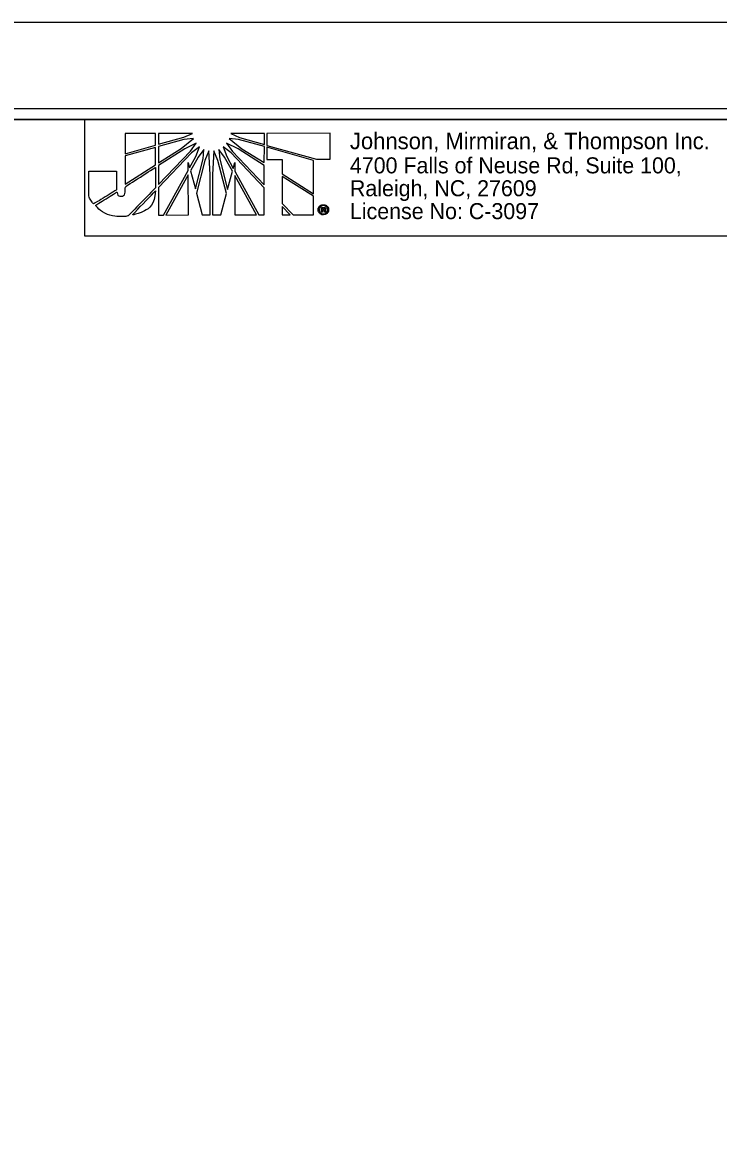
# Model space of a CAD drawing. Extents: x 1640342 to 1730599, y 538663 to 843747.
# Drawn here: x 1730101.1 to 1730133.5, y 540303.4 to 540355.9 of the extents above; entities that cross this region are included whole.
import ezdxf

# ---------------------------------------------------------------- set-up
doc = ezdxf.new("R2010")
doc.units = 0
for name, color, linetype in [('Prop Dimension Text', 7, 'Continuous'), ('Sheet Plan CELL', 7, 'Continuous'), ('Sheet Plot Border Inside CELL', 7, 'Continuous'), ('Sheet Plot Border Outside CELL', 7, 'Continuous')]:
    doc.layers.add(name, color=color, linetype=linetype)

msp = doc.modelspace()

# ---------------------------------------------------------------- linework, layer by layer
at = {"layer": 'Prop Dimension Text'}
for p, q in [((1730107.302, 540350.759), (1730105.899, 540350.758)), ((1730105.899, 540350.758), (1730105.9, 540349.827)), ((1730107.302, 540350.218), (1730107.302, 540350.759)), ((1730109.027, 540350.768), (1730107.448, 540350.767)), ((1730107.448, 540350.767), (1730107.448, 540350.264)), ((1730107.448, 540350.264), (1730108.624, 540350.589)), ((1730108.624, 540350.589), (1730109.027, 540350.768)), ((1730112.37, 540350.764), (1730110.814, 540350.77)), ((1730110.814, 540350.77), (1730111.208, 540350.585)), ((1730111.208, 540350.585), (1730112.37, 540350.26)), ((1730112.37, 540350.26), (1730112.37, 540350.764)), ((1730115.428, 540350.774), (1730112.479, 540350.771)), ((1730112.479, 540350.771), (1730112.479, 540350.23)), ((1730115.43, 540349.566), (1730115.428, 540350.774)), ((1730105.9, 540349.827), (1730107.302, 540350.218)), ((1730107.302, 540350.116), (1730105.9, 540349.721)), ((1730107.303, 540349.303), (1730107.302, 540350.116)), ((1730108.624, 540350.481), (1730107.448, 540350.155)), ((1730107.448, 540350.155), (1730107.449, 540349.396)), ((1730107.449, 540349.396), (1730108.502, 540350.064)), ((1730108.664, 540350.048), (1730107.449, 540349.273)), ((1730108.502, 540350.064), (1730109.082, 540350.537)), ((1730109.082, 540350.537), (1730108.624, 540350.481)), ((1730109.198, 540350.319), (1730108.664, 540350.048)), ((1730108.928, 540349.939), (1730109.198, 540350.319)), ((1730109.361, 540350.15), (1730108.988, 540349.863)), ((1730109.19, 540349.701), (1730109.361, 540350.15)), ((1730110.449, 540350.151), (1730110.621, 540349.702)), ((1730110.822, 540349.864), (1730110.449, 540350.151)), ((1730110.613, 540350.32), (1730110.884, 540349.934)), ((1730111.155, 540350.05), (1730110.613, 540350.32)), ((1730110.736, 540350.538), (1730111.324, 540350.057)), ((1730111.169, 540350.483), (1730110.736, 540350.538)), ((1730112.362, 540349.285), (1730111.155, 540350.05)), ((1730112.37, 540350.153), (1730111.169, 540350.483)), ((1730111.324, 540350.057), (1730112.362, 540349.41)), ((1730112.362, 540349.41), (1730112.37, 540350.153)), ((1730112.479, 540350.23), (1730112.479, 540350.213)), ((1730112.479, 540350.213), (1730114.802, 540349.565)), ((1730112.479, 540350.13), (1730112.479, 540350.121)), ((1730114.654, 540349.512), (1730112.479, 540350.13)), ((1730112.479, 540350.121), (1730112.48, 540349.556)), ((1730105.9, 540349.721), (1730105.901, 540348.413)), ((1730107.45, 540348.398), (1730108.928, 540349.939)), ((1730108.988, 540349.863), (1730107.45, 540348.25)), ((1730108.896, 540349.166), (1730109.19, 540349.701)), ((1730109.285, 540349.668), (1730108.936, 540349.034)), ((1730109.161, 540348.191), (1730109.523, 540349.592)), ((1730109.562, 540350.025), (1730109.285, 540349.668)), ((1730109.523, 540349.592), (1730109.562, 540350.025)), ((1730109.794, 540349.963), (1730109.602, 540349.514)), ((1730109.855, 540348.856), (1730109.794, 540349.963)), ((1730110.025, 540349.963), (1730109.954, 540348.856)), ((1730110.211, 540349.514), (1730110.025, 540349.963)), ((1730110.25, 540350.026), (1730110.296, 540349.577)), ((1730110.521, 540349.67), (1730110.25, 540350.026)), ((1730110.296, 540349.577), (1730110.661, 540348.16)), ((1730110.885, 540349.012), (1730110.521, 540349.67)), ((1730110.621, 540349.702), (1730110.922, 540349.144)), ((1730112.363, 540348.241), (1730110.822, 540349.864)), ((1730110.884, 540349.934), (1730112.363, 540348.386)), ((1730112.48, 540349.556), (1730113.2, 540349.556)), ((1730113.2, 540349.556), (1730113.201, 540348.883)), ((1730114.802, 540349.565), (1730115.43, 540349.566)), ((1730105.901, 540348.413), (1730107.303, 540349.303)), ((1730107.449, 540349.273), (1730107.45, 540348.398)), ((1730107.683, 540346.977), (1730108.827, 540349.05)), ((1730108.827, 540349.05), (1730108.826, 540349.42)), ((1730108.826, 540349.42), (1730108.896, 540349.166)), ((1730108.936, 540349.034), (1730109.161, 540348.191)), ((1730109.602, 540349.514), (1730109.208, 540347.997)), ((1730110.615, 540347.975), (1730110.211, 540349.514)), ((1730110.661, 540348.16), (1730110.885, 540349.012)), ((1730110.922, 540349.144), (1730110.994, 540349.422)), ((1730110.994, 540349.422), (1730110.994, 540349.013)), ((1730110.994, 540349.013), (1730112.116, 540346.981)), ((1730112.363, 540348.386), (1730112.362, 540349.285)), ((1730114.655, 540347.963), (1730114.654, 540349.512)), ((1730108.827, 540348.848), (1730107.792, 540346.977)), ((1730108.838, 540346.978), (1730108.827, 540348.848)), ((1730109.857, 540346.986), (1730109.855, 540348.856)), ((1730109.954, 540348.856), (1730109.956, 540346.986)), ((1730112.001, 540346.988), (1730110.994, 540348.811)), ((1730110.994, 540348.811), (1730110.996, 540346.987)), ((1730113.201, 540348.883), (1730114.655, 540347.963)), ((1730113.201, 540348.767), (1730113.202, 540347.512)), ((1730114.655, 540347.854), (1730113.201, 540348.767)), ((1730107.45, 540348.25), (1730107.451, 540346.976)), ((1730109.208, 540347.997), (1730109.472, 540346.985)), ((1730110.345, 540346.986), (1730110.615, 540347.975)), ((1730112.364, 540346.981), (1730112.363, 540348.241)), ((1730113.202, 540347.512), (1730113.705, 540346.982)), ((1730114.656, 540346.983), (1730114.655, 540347.854)), ((1730115.113, 540347.457), (1730115.113, 540347.413)), ((1730115.113, 540347.413), (1730115.113, 540347.457)), ((1730107.451, 540346.976), (1730107.683, 540346.977)), ((1730107.792, 540346.977), (1730108.838, 540346.978)), ((1730109.472, 540346.985), (1730109.857, 540346.986)), ((1730109.956, 540346.986), (1730110.345, 540346.986)), ((1730110.996, 540346.987), (1730112.001, 540346.988)), ((1730112.116, 540346.981), (1730112.364, 540346.981)), ((1730113.566, 540346.982), (1730113.202, 540347.375)), ((1730113.202, 540347.375), (1730113.202, 540346.982)), ((1730113.202, 540346.982), (1730113.566, 540346.982)), ((1730113.705, 540346.982), (1730114.656, 540346.983)), ((1730115.026, 540347.116), (1730115.025, 540347.331)), ((1730115.025, 540347.331), (1730115.113, 540347.331)), ((1730115.074, 540347.116), (1730115.026, 540347.116)), ((1730115.113, 540347.29), (1730115.074, 540347.29)), ((1730115.074, 540347.29), (1730115.074, 540347.239)), ((1730115.074, 540347.239), (1730115.113, 540347.239)), ((1730115.113, 540347.2), (1730115.074, 540347.2)), ((1730115.074, 540347.2), (1730115.074, 540347.116)), ((1730115.113, 540347.331), (1730115.113, 540347.29)), ((1730115.113, 540347.29), (1730115.113, 540347.331)), ((1730115.113, 540347.331), (1730115.127, 540347.331)), ((1730115.119, 540347.29), (1730115.113, 540347.29)), ((1730115.113, 540347.239), (1730115.113, 540347.2)), ((1730115.113, 540347.2), (1730115.113, 540347.239)), ((1730115.113, 540347.239), (1730115.115, 540347.239)), ((1730115.115, 540347.2), (1730115.113, 540347.2)), ((1730115.113, 540347.032), (1730115.114, 540346.985)), ((1730115.114, 540346.985), (1730115.113, 540347.032)), ((1730115.113, 540347.032), (1730115.115, 540347.032)), ((1730115.115, 540346.985), (1730115.114, 540346.985))]:
    msp.add_line(p, q, dxfattribs=at)
msp.add_lwpolyline([(1730104.001, 540346.012), (1730133.983, 540346.012), (1730133.983, 540351.422), (1730104.001, 540351.422)], close=True, dxfattribs=at)
for points in [[(1730105.9, 540349.827), (1730107.302, 540350.218), (1730107.302, 540350.759), (1730105.899, 540350.758), (1730105.9, 540349.827)], [(1730108.624, 540350.589), (1730109.027, 540350.768), (1730107.448, 540350.767), (1730107.448, 540350.264), (1730108.624, 540350.589)], [(1730111.208, 540350.585), (1730112.37, 540350.26), (1730112.37, 540350.764), (1730110.814, 540350.77), (1730111.208, 540350.585)], [(1730115.428, 540350.774), (1730112.479, 540350.771), (1730112.479, 540350.23), (1730112.479, 540350.213), (1730114.802, 540349.565), (1730115.43, 540349.566), (1730115.428, 540350.774)], [(1730105.901, 540348.413), (1730107.303, 540349.303), (1730107.302, 540350.116), (1730105.9, 540349.721), (1730105.901, 540348.413)], [(1730107.448, 540350.155), (1730107.449, 540349.396), (1730108.502, 540350.064), (1730109.082, 540350.537), (1730108.624, 540350.481), (1730107.448, 540350.155)], [(1730107.449, 540349.273), (1730107.45, 540348.398), (1730108.928, 540349.939), (1730109.198, 540350.319), (1730108.664, 540350.048), (1730107.449, 540349.273)], [(1730109.361, 540350.15), (1730108.988, 540349.863), (1730107.45, 540348.25), (1730107.451, 540346.976), (1730107.683, 540346.977), (1730108.827, 540349.05), (1730108.826, 540349.42), (1730108.896, 540349.166), (1730109.19, 540349.701), (1730109.361, 540350.15)], [(1730110.449, 540350.151), (1730110.621, 540349.702), (1730110.922, 540349.144), (1730110.994, 540349.422), (1730110.994, 540349.013), (1730112.116, 540346.981), (1730112.364, 540346.981), (1730112.363, 540348.241), (1730110.822, 540349.864), (1730110.449, 540350.151)], [(1730110.613, 540350.32), (1730110.884, 540349.934), (1730112.363, 540348.386), (1730112.362, 540349.285), (1730111.155, 540350.05), (1730110.613, 540350.32)], [(1730110.736, 540350.538), (1730111.324, 540350.057), (1730112.362, 540349.41), (1730112.37, 540350.153), (1730111.169, 540350.483), (1730110.736, 540350.538)], [(1730112.479, 540350.13), (1730112.479, 540350.121), (1730112.48, 540349.556), (1730113.2, 540349.556), (1730113.201, 540348.883), (1730114.655, 540347.963), (1730114.654, 540349.512), (1730112.479, 540350.13)], [(1730109.562, 540350.025), (1730109.285, 540349.668), (1730108.936, 540349.034), (1730109.161, 540348.191), (1730109.523, 540349.592), (1730109.562, 540350.025)], [(1730109.602, 540349.514), (1730109.208, 540347.997), (1730109.472, 540346.985), (1730109.857, 540346.986), (1730109.855, 540348.856), (1730109.794, 540349.963), (1730109.602, 540349.514)], [(1730110.025, 540349.963), (1730109.954, 540348.856), (1730109.956, 540346.986), (1730110.345, 540346.986), (1730110.615, 540347.975), (1730110.211, 540349.514), (1730110.025, 540349.963)], [(1730110.25, 540350.026), (1730110.296, 540349.577), (1730110.661, 540348.16), (1730110.885, 540349.012), (1730110.521, 540349.67), (1730110.25, 540350.026)], [(1730107.792, 540346.977), (1730108.838, 540346.978), (1730108.827, 540348.848), (1730107.792, 540346.977)], [(1730110.996, 540346.987), (1730112.001, 540346.988), (1730110.994, 540348.811), (1730110.996, 540346.987)], [(1730113.201, 540348.767), (1730113.202, 540347.512), (1730113.705, 540346.982), (1730114.656, 540346.983), (1730114.655, 540347.854), (1730113.201, 540348.767), (1730113.201, 540348.767)], [(1730113.202, 540346.982), (1730113.202, 540346.982), (1730113.566, 540346.982), (1730113.202, 540347.375), (1730113.202, 540346.982)], [(1730115.207, 540347.167), (1730115.207, 540347.155), (1730115.209, 540347.147), (1730115.209, 540347.14), (1730115.215, 540347.116), (1730115.17, 540347.116)]]:
    msp.add_lwpolyline(points, dxfattribs=at)
for points, degree in [([(1730105.497, 540349.014), (1730105.497, 540349.014), (1730104.199, 540349.013), (1730104.199, 540349.013), (1730104.199, 540349.013), (1730104.199, 540348.2), (1730104.199, 540348.2), (1730104.199, 540348.2), (1730104.199, 540348.115), (1730104.199, 540348.115), (1730104.2, 540347.86), (1730104.283, 540347.659), (1730104.432, 540347.49), (1730104.432, 540347.49), (1730105.498, 540348.139), (1730105.498, 540348.155), (1730105.498, 540348.155), (1730105.497, 540349.014), (1730105.497, 540349.014)], 3), ([(1730105.7, 540347.845), (1730105.617, 540347.845), (1730105.545, 540347.891), (1730105.515, 540348.047), (1730105.515, 540348.047), (1730104.508, 540347.423), (1730104.508, 540347.423), (1730104.819, 540347.097), (1730105.314, 540346.903), (1730105.733, 540346.903), (1730105.842, 540346.903), (1730105.925, 540346.912), (1730106.041, 540346.936), (1730106.041, 540346.936), (1730107.304, 540348.243), (1730107.304, 540348.243), (1730107.304, 540348.243), (1730107.303, 540349.187), (1730107.303, 540349.187), (1730107.303, 540349.187), (1730105.901, 540348.295), (1730105.901, 540348.295), (1730105.901, 540347.94), (1730105.816, 540347.845), (1730105.7, 540347.845)], 3), ([(1730105.7, 540347.845), (1730105.617, 540347.845), (1730105.545, 540347.891), (1730105.515, 540348.047), (1730105.515, 540348.047), (1730104.508, 540347.423), (1730104.508, 540347.423), (1730104.819, 540347.097), (1730105.314, 540346.903), (1730105.733, 540346.903), (1730105.842, 540346.903), (1730105.925, 540346.912), (1730106.041, 540346.936), (1730106.041, 540346.936), (1730107.304, 540348.243), (1730107.304, 540348.243), (1730107.304, 540348.243), (1730107.303, 540349.187), (1730107.303, 540349.187), (1730107.303, 540349.187), (1730105.901, 540348.295), (1730105.901, 540348.295), (1730105.901, 540347.94), (1730105.816, 540347.845), (1730105.7, 540347.845)], 3), ([(1730107.304, 540348.095), (1730107.304, 540348.095), (1730106.212, 540346.966), (1730106.212, 540346.966), (1730106.747, 540347.098), (1730107.279, 540347.453), (1730107.304, 540348.095)], 3), ([(1730115.114, 540346.985), (1730115.049, 540346.985), (1730114.993, 540347.009), (1730114.946, 540347.056), (1730114.899, 540347.1), (1730114.875, 540347.157), (1730114.875, 540347.223), (1730114.875, 540347.289), (1730114.899, 540347.346), (1730114.945, 540347.389), (1730114.992, 540347.434), (1730115.047, 540347.457), (1730115.113, 540347.457)], 3), ([(1730115.113, 540347.457), (1730115.179, 540347.457), (1730115.236, 540347.434), (1730115.283, 540347.389), (1730115.33, 540347.346), (1730115.353, 540347.29), (1730115.353, 540347.224)], 3), ([(1730115.113, 540347.413), (1730115.06, 540347.412), (1730115.016, 540347.395), (1730114.979, 540347.36), (1730114.942, 540347.323), (1730114.922, 540347.276), (1730114.922, 540347.223), (1730114.922, 540347.171), (1730114.942, 540347.124), (1730114.979, 540347.087), (1730115.016, 540347.05), (1730115.061, 540347.032), (1730115.113, 540347.032)], 3), ([(1730115.115, 540347.032), (1730115.168, 540347.032), (1730115.213, 540347.05), (1730115.25, 540347.087), (1730115.287, 540347.124), (1730115.306, 540347.171), (1730115.306, 540347.224), (1730115.306, 540347.276), (1730115.287, 540347.323), (1730115.25, 540347.36), (1730115.213, 540347.395), (1730115.168, 540347.413), (1730115.113, 540347.413)], 3), ([(1730115.115, 540347.239), (1730115.146, 540347.239), (1730115.162, 540347.249), (1730115.162, 540347.266), (1730115.162, 540347.282), (1730115.148, 540347.29), (1730115.119, 540347.29)], 3), ([(1730115.353, 540347.224), (1730115.353, 540347.157), (1730115.33, 540347.101), (1730115.285, 540347.054), (1730115.238, 540347.009), (1730115.182, 540346.986), (1730115.115, 540346.985)], 3), ([(1730115.152, 540347.192), (1730115.146, 540347.196), (1730115.135, 540347.2), (1730115.115, 540347.2)], 2), ([(1730115.127, 540347.331), (1730115.181, 540347.331), (1730115.209, 540347.309), (1730115.209, 540347.266), (1730115.209, 540347.247), (1730115.201, 540347.231), (1730115.184, 540347.22)], 3), ([(1730115.17, 540347.116), (1730115.164, 540347.128), (1730115.16, 540347.14), (1730115.16, 540347.155), (1730115.16, 540347.175), (1730115.158, 540347.186), (1730115.152, 540347.192)], 3), ([(1730115.184, 540347.22), (1730115.197, 540347.212), (1730115.205, 540347.194), (1730115.207, 540347.167)], 2)]:
    msp.add_open_spline(points, degree=degree, dxfattribs=at)
at = {"layer": 'Sheet Plan CELL'}
for points in [[(1729873.99, 540141.419), (1729873.985, 540351.414), (1730133.983, 540351.422), (1730133.985, 540321.409), (1730173.993, 540321.407), (1730173.993, 540141.419)], [(1730173.998, 540351.419), (1729873.99, 540351.419), (1729873.99, 540141.419), (1730173.993, 540141.419)]]:
    msp.add_lwpolyline(points, close=True, dxfattribs=at)
at = {"layer": 'Sheet Plot Border Inside CELL'}
msp.add_lwpolyline([(1729843.293, 540140.917), (1730176.49, 540140.919), (1730176.493, 540351.917), (1729843.293, 540351.917)], close=True, dxfattribs=at)
at = {"layer": 'Sheet Plot Border Outside CELL'}
msp.add_lwpolyline([(1729840.693, 540136.917), (1730177.393, 540136.917), (1730177.393, 540355.917), (1729840.693, 540355.917)], close=True, dxfattribs=at)

# ---------------------------------------------------------------- texts
at = {"layer": 'Prop Dimension Text'}
for s, height, p in [('Johnson, Mirmiran, & Thompson Inc.', 0.76607, (1730116.348, 540350.036)), ('4700 Falls of Neuse Rd, Suite 100, ', 0.74418, (1730116.348, 540348.912)), ('Raleigh, NC, 27609', 0.74418, (1730116.348, 540347.849)), ('License No: C-3097', 0.74418, (1730116.348, 540346.785))]:
    msp.add_text(s, height=height, rotation=360, dxfattribs=at).set_placement(p)

doc.saveas('drawing.dxf')
